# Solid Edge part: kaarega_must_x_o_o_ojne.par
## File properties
Author: Romil
Template: iso part.par
Last saved by: Romil
Revision: 40
Application: Solid Edge
Accuracy: 0.990
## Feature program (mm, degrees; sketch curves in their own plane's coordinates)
sketch for "unnamed Protrusion 1" plane through (0, 0, 0) normal (1, 0, 0) x-axis (0, 1, 0)
  line (-0.25, -3.6) -> (-7.75, -3.6)
  line (-7.75, -3.6) -> (-8, -3.6)
  arc centre (-8, 0) radius 3.6 from (-8, 3.6) to (-8, -3.6) ccw
  line (-7.75, 3.6) -> (-8, 3.6)
  line (-0.25, 3.6) -> (-7.75, 3.6)
  line (-0.25, 3.6) -> (0, 3.6)
  line (0, 3.6) -> (38.5088, 3.6)
  line (52.4, 17.4912) -> (38.5088, 3.6)
  line (52.4, 17.4912) -> (52.4, 32)
  line (59.6, 16) -> (59.6, 32)
  line (58.5456, 13.4544) -> (42.5456, -2.5456)
  line (0, -3.6) -> (40, -3.6)
  line (-0.25, -3.6) -> (0, -3.6)
extrude "unnamed Protrusion 1" add finite 7.8 along -normal
sketch for "ExtrudedCutout_39" #1 plane through (0, 0, 0) normal (1, 0, 0) x-axis (0, 1, 0)
  line (0, 0) -> (0, 0)
  line (0, 0) -> (0, 0)
  circle centre (56, 24) radius 2.4
sketch for "ExtrudedCutout_39" #2 plane through (0, 0, 0) normal (1, 0, 0) x-axis (0, 1, 0)
  arc centre (56.975, 31.025) radius 0.1 from (56.875, 31.025) to (56.975, 31.125) cw
  line (56.975, 31.125) -> (58.0449, 31.125)
  line (58.0449, 31.125) -> (58.181, 31.125)
  arc centre (56, 32) radius 2.35 from (58.181, 31.125) to (58.181, 32.875) ccw
  line (58.181, 32.875) -> (58.0449, 32.875)
  line (58.0449, 32.875) -> (56.975, 32.875)
  arc centre (56.975, 32.975) radius 0.1 from (56.975, 32.875) to (56.875, 32.975) cw
  line (56.875, 32.975) -> (56.875, 34.0449)
  line (56.875, 34.0449) -> (56.875, 34.181)
  arc centre (56, 32) radius 2.35 from (56.875, 34.181) to (55.125, 34.181) ccw
  line (55.125, 34.181) -> (55.125, 34.0449)
  line (55.125, 34.0449) -> (55.125, 32.975)
  arc centre (55.025, 32.975) radius 0.1 from (55.125, 32.975) to (55.025, 32.875) cw
  line (55.025, 32.875) -> (53.9551, 32.875)
  line (53.9551, 32.875) -> (53.819, 32.875)
  arc centre (56, 32) radius 2.35 from (53.819, 32.875) to (53.819, 31.125) ccw
  line (53.819, 31.125) -> (53.9551, 31.125)
  line (53.9551, 31.125) -> (55.025, 31.125)
  arc centre (55.025, 31.025) radius 0.1 from (55.025, 31.125) to (55.125, 31.025) cw
  line (55.125, 31.025) -> (55.125, 29.9551)
  line (55.125, 29.9551) -> (55.125, 28.9163)
  arc centre (54.825, 28.9163) radius 0.3 from (54.7182, 28.6359) to (55.125, 28.9163) ccw
  arc centre (56, 32) radius 3.6 from (54.7182, 28.6359) to (53.7108, 29.2216) cw
  arc centre (53.52, 28.9901) radius 0.3 from (53.7108, 29.2216) to (53.22, 28.9901) ccw
  line (53.22, 28.9901) -> (53.22, 26.9696)
  arc centre (53.52, 26.9696) radius 0.3 from (53.22, 26.9696) to (53.7108, 26.7381) ccw
  arc centre (56, 23.9597) radius 3.6 from (53.7108, 26.7381) to (58.2892, 26.7381) cw
  arc centre (58.48, 26.9696) radius 0.3 from (58.2892, 26.7381) to (58.78, 26.9696) ccw
  line (58.78, 28.9901) -> (58.78, 26.9696)
  arc centre (58.48, 28.9901) radius 0.3 from (58.78, 28.9901) to (58.2892, 29.2216) ccw
  arc centre (56, 32) radius 3.6 from (58.2892, 29.2216) to (57.2818, 28.6359) cw
  arc centre (57.175, 28.9163) radius 0.3 from (56.875, 28.9163) to (57.2818, 28.6359) ccw
  line (56.875, 28.9163) -> (56.875, 29.9551)
  line (56.875, 29.9551) -> (56.875, 31.025)
sketch for "ExtrudedCutout_39" #3 plane through (0, 0, 0) normal (1, 0, 0) x-axis (0, 1, 0)
  circle centre (56, 16) radius 2.4
sketch for "ExtrudedCutout_39" #4 plane through (0, 0, 0) normal (1, 0, 0) x-axis (0, 1, 0)
  line (47.3539, 3.9598) -> (52.0402, 8.6461)
  line (48.6461, 12.0402) -> (43.9598, 7.3539)
sketch for "ExtrudedCutout_39" #5 plane through (0, 0, 0) normal (1, 0, 0) x-axis (0, 1, 0)
  circle centre (40, 0) radius 2.4
sketch for "ExtrudedCutout_39" #6 plane through (0, 0, 0) normal (1, 0, 0) x-axis (0, 1, 0)
  circle centre (32, 0) radius 2.4
sketch for "ExtrudedCutout_39" #7 plane through (0, 0, 0) normal (1, 0, 0) x-axis (0, 1, 0)
  circle centre (24, 0) radius 2.4
sketch for "ExtrudedCutout_39" #8 plane through (0, 0, 0) normal (1, 0, 0) x-axis (0, 1, 0)
  circle centre (16, 0) radius 2.4
sketch for "ExtrudedCutout_39" #9 plane through (0, 0, 0) normal (1, 0, 0) x-axis (0, 1, 0)
  circle centre (8, 0) radius 2.4
sketch for "ExtrudedCutout_39" #10 plane through (0, 0, 0) normal (1, 0, 0) x-axis (0, 1, 0)
  circle centre (0, 0) radius 2.4
sketch for "ExtrudedCutout_39" #11 plane through (0, 0, 0) normal (1, 0, 0) x-axis (0, 1, 0)
  line (-5.9551, 0.875) -> (-7.025, 0.875)
  arc centre (-7.025, 0.975) radius 0.1 from (-7.025, 0.875) to (-7.125, 0.975) cw
  line (-7.125, 0.975) -> (-7.125, 2.0449)
  line (-7.125, 2.0449) -> (-7.125, 2.181)
  arc centre (-8, 0) radius 2.35 from (-7.125, 2.181) to (-8.875, 2.181) ccw
  line (-8.875, 2.181) -> (-8.875, 2.0449)
  line (-8.875, 2.0449) -> (-8.875, 0.975)
  arc centre (-8.975, 0.975) radius 0.1 from (-8.875, 0.975) to (-8.975, 0.875) cw
  line (-8.975, 0.875) -> (-10.0449, 0.875)
  line (-10.0449, 0.875) -> (-10.181, 0.875)
  arc centre (-8, 0) radius 2.35 from (-10.181, 0.875) to (-10.181, -0.875) ccw
  line (-10.181, -0.875) -> (-10.0449, -0.875)
  line (-10.0449, -0.875) -> (-8.975, -0.875)
  arc centre (-8.975, -0.975) radius 0.1 from (-8.975, -0.875) to (-8.875, -0.975) cw
  line (-8.875, -0.975) -> (-8.875, -2.0449)
  line (-8.875, -2.0449) -> (-8.875, -2.181)
  arc centre (-8, 0) radius 2.35 from (-8.875, -2.181) to (-7.125, -2.181) ccw
  line (-7.125, -2.181) -> (-7.125, -2.0449)
  line (-7.125, -2.0449) -> (-7.125, -0.975)
  arc centre (-7.025, -0.975) radius 0.1 from (-7.125, -0.975) to (-7.025, -0.875) cw
  line (-7.025, -0.875) -> (-5.9551, -0.875)
  line (-5.9551, -0.875) -> (-4.9163, -0.875)
  arc centre (-4.9163, -1.175) radius 0.3 from (-4.6359, -1.2818) to (-4.9163, -0.875) ccw
  arc centre (-8, 0) radius 3.6 from (-4.6359, -1.2818) to (-5.2216, -2.2892) cw
  arc centre (-4.9901, -2.48) radius 0.3 from (-5.2216, -2.2892) to (-4.9901, -2.78) ccw
  line (-4.9901, -2.78) -> (-2.9696, -2.78)
  arc centre (-2.9696, -2.48) radius 0.3 from (-2.9696, -2.78) to (-2.7381, -2.2892) ccw
  arc centre (0.0403, 0) radius 3.6 from (-2.7381, -2.2892) to (-2.7381, 2.2892) cw
  arc centre (-2.9696, 2.48) radius 0.3 from (-2.7381, 2.2892) to (-2.9696, 2.78) ccw
  line (-4.9901, 2.78) -> (-2.9696, 2.78)
  arc centre (-4.9901, 2.48) radius 0.3 from (-4.9901, 2.78) to (-5.2216, 2.2892) ccw
  arc centre (-8, 0) radius 3.6 from (-5.2216, 2.2892) to (-4.6359, 1.2818) cw
  arc centre (-4.9163, 1.175) radius 0.3 from (-4.9163, 0.875) to (-4.6359, 1.2818) ccw
  line (-4.9163, 0.875) -> (-5.9551, 0.875)
extrude "ExtrudedCutout_39" cut finite 28.9643 along -normal
sketch for "ExtrudedCutout_40" #1 plane through (0, 0, 0) normal (1, 0, 0) x-axis (0, 1, 0)
  arc centre (8, 0) radius 3.6 from (5.2216, 2.2892) to (5.2216, -2.2892) ccw
  arc centre (4.9901, -2.48) radius 0.3 from (5.2216, -2.2892) to (4.9901, -2.78) cw
  arc centre (4.0207, -135.1567) radius 132.3803 from (3.0524, -2.78) to (4.9901, -2.78) cw
  arc centre (3.0502, -2.48) radius 0.3 from (2.8187, -2.2892) to (3.0524, -2.78) ccw
  arc centre (3.0502, 2.48) radius 0.3 from (3.0524, 2.78) to (2.8187, 2.2892) ccw
  arc centre (4.0207, 135.1567) radius 132.3803 from (3.0524, 2.78) to (4.9901, 2.78) ccw
  arc centre (4.9901, 2.48) radius 0.3 from (4.9901, 2.78) to (5.2216, 2.2892) cw
sketch for "ExtrudedCutout_40" #2 plane through (0, 0, 0) normal (1, 0, 0) x-axis (0, 1, 0)
  arc centre (12.0207, -135.1567) radius 132.3803 from (11.0524, -2.78) to (12.9901, -2.78) cw
  arc centre (12.9901, -2.48) radius 0.3 from (13.2216, -2.2892) to (12.9901, -2.78) cw
  arc centre (16, 0) radius 3.6 from (13.2216, 2.2892) to (13.2216, -2.2892) ccw
  arc centre (12.9901, 2.48) radius 0.3 from (12.9901, 2.78) to (13.2216, 2.2892) cw
  arc centre (12.0207, 135.1567) radius 132.3803 from (11.0524, 2.78) to (12.9901, 2.78) ccw
  arc centre (11.0502, 2.48) radius 0.3 from (11.0524, 2.78) to (10.8187, 2.2892) ccw
  arc centre (8.0403, 0) radius 3.6 from (10.8187, 2.2892) to (10.8187, -2.2892) cw
  arc centre (11.0502, -2.48) radius 0.3 from (10.8187, -2.2892) to (11.0524, -2.78) ccw
sketch for "ExtrudedCutout_40" #3 plane through (0, 0, 0) normal (1, 0, 0) x-axis (0, 1, 0)
  arc centre (16.0403, 0) radius 3.6 from (18.8187, 2.2892) to (18.8187, -2.2892) cw
  arc centre (19.0502, -2.48) radius 0.3 from (18.8187, -2.2892) to (19.0524, -2.78) ccw
  arc centre (20.0207, -135.1567) radius 132.3803 from (19.0524, -2.78) to (20.9901, -2.78) cw
  arc centre (20.9901, -2.48) radius 0.3 from (21.2216, -2.2892) to (20.9901, -2.78) cw
  arc centre (24, 0) radius 3.6 from (21.2216, 2.2892) to (21.2216, -2.2892) ccw
  arc centre (20.9901, 2.48) radius 0.3 from (20.9901, 2.78) to (21.2216, 2.2892) cw
  arc centre (20.0207, 135.1567) radius 132.3803 from (19.0524, 2.78) to (20.9901, 2.78) ccw
  arc centre (19.0502, 2.48) radius 0.3 from (19.0524, 2.78) to (18.8187, 2.2892) ccw
sketch for "ExtrudedCutout_40" #4 plane through (0, 0, 0) normal (1, 0, 0) x-axis (0, 1, 0)
  arc centre (32, 0) radius 3.6 from (29.2216, 2.2892) to (29.2216, -2.2892) ccw
  arc centre (28.9901, -2.48) radius 0.3 from (29.2216, -2.2892) to (28.9901, -2.78) cw
  arc centre (28.0207, -135.1567) radius 132.3803 from (27.0524, -2.78) to (28.9901, -2.78) cw
  arc centre (27.0502, -2.48) radius 0.3 from (26.8187, -2.2892) to (27.0524, -2.78) ccw
  arc centre (24.0403, 0) radius 3.6 from (26.8187, 2.2892) to (26.8187, -2.2892) cw
  arc centre (27.0502, 2.48) radius 0.3 from (27.0524, 2.78) to (26.8187, 2.2892) ccw
  arc centre (28.0207, 135.1567) radius 132.3803 from (27.0524, 2.78) to (28.9901, 2.78) ccw
  arc centre (28.9901, 2.48) radius 0.3 from (28.9901, 2.78) to (29.2216, 2.2892) cw
sketch for "ExtrudedCutout_40" #5 plane through (0, 0, 0) normal (1, 0, 0) x-axis (0, 1, 0)
  arc centre (36.9901, -2.48) radius 0.3 from (37.2216, -2.2892) to (36.9901, -2.78) cw
  arc centre (36.0207, -135.1567) radius 132.3803 from (35.0524, -2.78) to (36.9901, -2.78) cw
  arc centre (35.0502, -2.48) radius 0.3 from (34.8187, -2.2892) to (35.0524, -2.78) ccw
  arc centre (32.0403, 0) radius 3.6 from (34.8187, 2.2892) to (34.8187, -2.2892) cw
  arc centre (35.0502, 2.48) radius 0.3 from (35.0524, 2.78) to (34.8187, 2.2892) ccw
  arc centre (36.0207, 135.1567) radius 132.3803 from (35.0524, 2.78) to (36.9901, 2.78) ccw
  arc centre (36.9901, 2.48) radius 0.3 from (36.9901, 2.78) to (37.2216, 2.2892) cw
  arc centre (40, 0) radius 3.6 from (37.2216, 2.2892) to (37.2216, -2.2892) ccw
sketch for "ExtrudedCutout_40" #6 plane through (0, 0, 0) normal (1, 0, 0) x-axis (0, 1, 0)
  arc centre (40.0285, 0.0285) radius 3.6 from (40.3744, 3.6118) to (43.6118, 0.3744) cw
  arc centre (43.9104, 0.4032) radius 0.3 from (43.6118, 0.3744) to (44.1241, 0.1926) ccw
  arc centre (138.4133, -92.7272) radius 132.3803 from (44.1241, 0.1926) to (45.4943, 1.5628) cw
  arc centre (45.2821, 1.7749) radius 0.3 from (45.311, 2.0735) to (45.4943, 1.5628) cw
  arc centre (45.6569, 5.6569) radius 3.6 from (42.0735, 5.311) to (45.311, 2.0735) ccw
  arc centre (41.7749, 5.2821) radius 0.3 from (41.5628, 5.4943) to (42.0735, 5.311) cw
  arc centre (-52.7272, 98.4133) radius 132.3803 from (40.1926, 4.1241) to (41.5628, 5.4943) ccw
  arc centre (40.4032, 3.9104) radius 0.3 from (40.1926, 4.1241) to (40.3744, 3.6118) ccw
sketch for "ExtrudedCutout_40" #7 plane through (0, 0, 0) normal (1, 0, 0) x-axis (0, 1, 0)
  arc centre (55.6253, 12.118) radius 0.3 from (55.6541, 12.4167) to (55.8374, 11.9059) cw
  arc centre (148.7564, -82.384) radius 132.3803 from (54.4673, 10.5358) to (55.8374, 11.9059) cw
  arc centre (54.2536, 10.7463) radius 0.3 from (53.955, 10.7175) to (54.4673, 10.5358) ccw
  arc centre (50.3716, 10.3716) radius 3.6 from (50.7175, 13.955) to (53.955, 10.7175) cw
  arc centre (50.7463, 14.2536) radius 0.3 from (50.5358, 14.4673) to (50.7175, 13.955) ccw
  arc centre (-42.384, 108.7564) radius 132.3803 from (50.5358, 14.4673) to (51.9059, 15.8374) ccw
  arc centre (52.118, 15.6253) radius 0.3 from (51.9059, 15.8374) to (52.4167, 15.6541) cw
  arc centre (56, 16) radius 3.6 from (52.4167, 15.6541) to (55.6541, 12.4167) ccw
sketch for "ExtrudedCutout_40" #8 plane through (0, 0, 0) normal (1, 0, 0) x-axis (0, 1, 0)
  arc centre (191.1567, 19.9793) radius 132.3803 from (58.78, 20.9476) to (58.78, 19.0099) ccw
  arc centre (58.48, 19.0099) radius 0.3 from (58.78, 19.0099) to (58.2892, 18.7784) cw
  arc centre (56, 16) radius 3.6 from (58.2892, 18.7784) to (53.7108, 18.7784) ccw
  arc centre (53.52, 19.0099) radius 0.3 from (53.7108, 18.7784) to (53.22, 19.0099) cw
  arc centre (-79.1567, 19.9793) radius 132.3803 from (53.22, 20.9476) to (53.22, 19.0099) cw
  arc centre (53.52, 20.9498) radius 0.3 from (53.7108, 21.1813) to (53.22, 20.9476) ccw
  arc centre (56, 23.9597) radius 3.6 from (58.2892, 21.1813) to (53.7108, 21.1813) cw
  arc centre (58.48, 20.9498) radius 0.3 from (58.78, 20.9476) to (58.2892, 21.1813) ccw
extrude "ExtrudedCutout_40" cut finite 3.4 along -normal
sketch for "unnamed Cutout 1" #1 plane through (0, 0, 0) normal (1, 0, 0) x-axis (0, 1, 0)
  circle centre (0, 0) radius 3.1
sketch for "unnamed Cutout 1" #2 plane through (0, 0, 0) normal (1, 0, 0) x-axis (0, 1, 0)
  circle centre (8, 0) radius 3.1
sketch for "unnamed Cutout 1" #3 plane through (0, 0, 0) normal (1, 0, 0) x-axis (0, 1, 0)
  circle centre (16, 0) radius 3.1
sketch for "unnamed Cutout 1" #4 plane through (0, 0, 0) normal (1, 0, 0) x-axis (0, 1, 0)
  circle centre (24, 0) radius 3.1
sketch for "unnamed Cutout 1" #5 plane through (0, 0, 0) normal (1, 0, 0) x-axis (0, 1, 0)
  circle centre (32, 0) radius 3.1
sketch for "unnamed Cutout 1" #6 plane through (0, 0, 0) normal (1, 0, 0) x-axis (0, 1, 0)
  circle centre (40, 0) radius 3.1
sketch for "unnamed Cutout 1" #7 plane through (0, 0, 0) normal (1, 0, 0) x-axis (0, 1, 0)
  line (43.4648, 7.8489) -> (48.1511, 12.5352)
  line (52.5352, 8.1511) -> (47.8489, 3.4648)
sketch for "unnamed Cutout 1" #8 plane through (0, 0, 0) normal (1, 0, 0) x-axis (0, 1, 0)
  circle centre (56, 16) radius 3.1
sketch for "unnamed Cutout 1" #9 plane through (0, 0, 0) normal (1, 0, 0) x-axis (0, 1, 0)
  circle centre (56, 24) radius 3.1
extrude "unnamed Cutout 1" cut finite 0.9 along -normal
mirror "unnamed Mirror 1" of "unnamed Cutout 1", "ExtrudedCutout_40" about plane through (-3.9, 0, 0) normal (1, 0, 0)
extrude "unnamed Cutout 2" cut finite 3.4
extrude "unnamed Cutout 3" cut finite 0.9
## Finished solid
Body 1: solid body, 262 faces, 654 edges, 404 vertices.
  Faces by surface: cylinder 194, plane 68
  Edges by curve: circle 388, line 266
Bounding box of the edges (mm): 7.800 x 71.200 x 39.200, from (-7.8, -11.6, -3.6) to (0, 59.6, 35.6).
Cylindrical faces by radius (mm): R0.1 x8, R0.3 x76, R2.35 x6, R2.4 x10, R3.1 x20, R3.6 x42, R132.3803 x32
Planar faces by outward normal: +x 18, +y 6, +z 6, -x 18, -y 6, -z 6, oblique 8
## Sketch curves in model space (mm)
circle centre (0, 56, 24) radius 2.4
circle centre (0, 56, 16) radius 2.4
circle centre (0, 40, 0) radius 2.4
circle centre (0, 56, 24) radius 3.1
circle centre (0, 32, 0) radius 3.1
circle centre (0, 32, 0) radius 2.4
circle centre (0, 24, 0) radius 3.1
circle centre (0, 24, 0) radius 2.4
circle centre (0, 16, 0) radius 3.1
circle centre (0, 16, 0) radius 2.4
circle centre (0, 40, 0) radius 3.1
circle centre (0, 56, 16) radius 3.1
circle centre (0, 0, 0) radius 2.4
circle centre (0, 8, 0) radius 3.1
circle centre (0, 0, 0) radius 3.1
circle centre (0, 8, 0) radius 2.4
arc centre (0, -8.975, 0.975) radius 0.1 from (0, -8.875, 0.975) through (0, -8.9064, 0.9023) to (0, -8.975, 0.875)
line (0, -8.975, 0.875) -> (0, -10.0449, 0.875)
line (0, -10.0449, 0.875) -> (0, -10.181, 0.875)
arc centre (0, -8, 0) radius 2.35 from (0, -10.181, 0.875) through (0, -10.35, 0) to (0, -10.181, -0.875)
line (0, -10.181, -0.875) -> (0, -10.0449, -0.875)
line (0, -10.0449, -0.875) -> (0, -8.975, -0.875)
arc centre (0, -8.975, -0.975) radius 0.1 from (0, -8.975, -0.875) through (0, -8.9023, -0.9064) to (0, -8.875, -0.975)
line (0, -8.875, -0.975) -> (0, -8.875, -2.0449)
line (0, -8.875, -2.0449) -> (0, -8.875, -2.181)
arc centre (0, -8, 0) radius 2.35 from (0, -8.875, -2.181) through (0, -8, -2.35) to (0, -7.125, -2.181)
line (0, -7.125, -2.181) -> (0, -7.125, -2.0449)
line (0, -7.125, -2.0449) -> (0, -7.125, -0.975)
arc centre (0, -7.025, -0.975) radius 0.1 from (0, -7.125, -0.975) through (0, -7.0936, -0.9023) to (0, -7.025, -0.875)
line (0, -7.025, -0.875) -> (0, -5.9551, -0.875)
line (0, -5.9551, -0.875) -> (0, -4.9163, -0.875)
arc centre (0, -4.9163, -1.175) radius 0.3 from (0, -4.6359, -1.2818) through (0, -4.6743, -0.9976) to (0, -4.9163, -0.875)
arc centre (0, -8, 0) radius 3.6 from (0, -4.6359, -1.2818) through (0, -4.8877, -1.8094) to (0, -5.2216, -2.2892)
arc centre (0, -4.9901, -2.48) radius 0.3 from (0, -5.2216, -2.2892) through (0, -5.2614, -2.608) to (0, -4.9901, -2.78)
line (0, -4.9901, -2.78) -> (0, -2.9696, -2.78)
arc centre (0, -2.9696, -2.48) radius 0.3 from (0, -2.9696, -2.78) through (0, -2.6983, -2.608) to (0, -2.7381, -2.2892)
arc centre (0, 0.0403, 0) radius 3.6 from (0, -2.7381, -2.2892) through (0, -3.5581, 0.1079) to (0, -2.7381, 2.2892)
arc centre (0, -2.9696, 2.48) radius 0.3 from (0, -2.7381, 2.2892) through (0, -2.6983, 2.608) to (0, -2.9696, 2.78)
line (0, -4.9901, 2.78) -> (0, -2.9696, 2.78)
arc centre (0, -4.9901, 2.48) radius 0.3 from (0, -4.9901, 2.78) through (0, -5.2614, 2.608) to (0, -5.2216, 2.2892)
arc centre (0, -8, 0) radius 3.6 from (0, -5.2216, 2.2892) through (0, -4.8877, 1.8094) to (0, -4.6359, 1.2818)
arc centre (0, -4.9163, 1.175) radius 0.3 from (0, -4.9163, 0.875) through (0, -4.6644, 1.0121) to (0, -4.6359, 1.2818)
line (0, -4.9163, 0.875) -> (0, -5.9551, 0.875)
line (0, -5.9551, 0.875) -> (0, -7.025, 0.875)
arc centre (0, -7.025, 0.975) radius 0.1 from (0, -7.025, 0.875) through (0, -7.0977, 0.9064) to (0, -7.125, 0.975)
line (0, -7.125, 0.975) -> (0, -7.125, 2.0449)
line (0, -7.125, 2.0449) -> (0, -7.125, 2.181)
arc centre (0, -8, 0) radius 2.35 from (0, -7.125, 2.181) through (0, -8, 2.35) to (0, -8.875, 2.181)
line (0, -8.875, 2.181) -> (0, -8.875, 2.0449)
line (0, -8.875, 2.0449) -> (0, -8.875, 0.975)
arc centre (0, 3.0502, -2.48) radius 0.3 from (0, 2.8187, -2.2892) through (0, 2.7793, -2.609) to (0, 3.0524, -2.78)
arc centre (0, 4.0207, -135.1567) radius 132.3803 from (0, 3.0524, -2.78) through (0, 4.0212, -2.7765) to (0, 4.9901, -2.78)
arc centre (0, 4.9901, -2.48) radius 0.3 from (0, 5.2216, -2.2892) through (0, 5.2614, -2.608) to (0, 4.9901, -2.78)
arc centre (0, 8, 0) radius 3.6 from (0, 5.2216, 2.2892) through (0, 4.4016, -0.1079) to (0, 5.2216, -2.2892)
arc centre (0, 4.9901, 2.48) radius 0.3 from (0, 4.9901, 2.78) through (0, 5.2614, 2.608) to (0, 5.2216, 2.2892)
arc centre (0, 4.0207, 135.1567) radius 132.3803 from (0, 3.0524, 2.78) through (0, 4.0212, 2.7765) to (0, 4.9901, 2.78)
arc centre (0, 3.0502, 2.48) radius 0.3 from (0, 3.0524, 2.78) through (0, 2.7793, 2.609) to (0, 2.8187, 2.2892)
arc centre (0, 0.0403, 0) radius 3.6 from (0, 2.8187, 2.2892) through (0, 3.6387, -0.1079) to (0, 2.8187, -2.2892)
line (0, -7.75, -3.6) -> (0, -8, -3.6)
line (0, -0.25, -3.6) -> (0, -7.75, -3.6)
line (0, -0.25, -3.6) -> (0, 0, -3.6)
line (0, 0, -3.6) -> (0, 40, -3.6)
arc centre (0, 40, 0) radius 3.6 from (0, 42.5456, -2.5456) through (0, 41.3777, -3.326) to (0, 40, -3.6)
line (0, 58.5456, 13.4544) -> (0, 42.5456, -2.5456)
arc centre (0, 56, 16) radius 3.6 from (0, 59.6, 16) through (0, 59.326, 14.6223) to (0, 58.5456, 13.4544)
line (0, 59.6, 16) -> (0, 59.6, 32)
arc centre (0, 56, 32) radius 3.6 from (0, 52.4, 32) through (0, 56.1067, 35.5984) to (0, 59.6, 32)
line (0, 52.4, 17.4912) -> (0, 52.4, 32)
line (0, 52.4, 17.4912) -> (0, 38.5088, 3.6)
line (0, 0, 3.6) -> (0, 38.5088, 3.6)
line (0, -0.25, 3.6) -> (0, 0, 3.6)
line (0, -0.25, 3.6) -> (0, -7.75, 3.6)
line (0, -7.75, 3.6) -> (0, -8, 3.6)
arc centre (0, -8, 0) radius 3.6 from (0, -8, 3.6) through (0, -11.5984, -0.1067) to (0, -8, -3.6)
arc centre (0, 50.3431, 10.3431) radius 3.1 from (0, 48.1511, 12.5352) through (0, 52.5992, 12.4693) to (0, 52.5352, 8.1511)
line (0, 52.5352, 8.1511) -> (0, 47.8489, 3.4648)
arc centre (0, 45.6569, 5.6569) radius 3.1 from (0, 47.8489, 3.4648) through (0, 43.4008, 3.5307) to (0, 43.4648, 7.8489)
line (0, 43.4648, 7.8489) -> (0, 48.1511, 12.5352)
arc centre (0, 45.6569, 5.6569) radius 2.4 from (0, 47.3539, 3.9598) through (0, 43.9103, 4.0108) to (0, 43.9598, 7.3539)
line (0, 47.3539, 3.9598) -> (0, 52.0402, 8.6461)
arc centre (0, 50.3431, 10.3431) radius 2.4 from (0, 48.6461, 12.0402) through (0, 52.0897, 11.9892) to (0, 52.0402, 8.6461)
line (0, 48.6461, 12.0402) -> (0, 43.9598, 7.3539)
arc centre (0, 11.0502, -2.48) radius 0.3 from (0, 10.8187, -2.2892) through (0, 10.7793, -2.609) to (0, 11.0524, -2.78)
arc centre (0, 12.0207, -135.1567) radius 132.3803 from (0, 11.0524, -2.78) through (0, 12.0212, -2.7765) to (0, 12.9901, -2.78)
arc centre (0, 12.9901, -2.48) radius 0.3 from (0, 13.2216, -2.2892) through (0, 13.2614, -2.608) to (0, 12.9901, -2.78)
arc centre (0, 16, 0) radius 3.6 from (0, 13.2216, 2.2892) through (0, 12.4016, -0.1079) to (0, 13.2216, -2.2892)
arc centre (0, 12.9901, 2.48) radius 0.3 from (0, 12.9901, 2.78) through (0, 13.2614, 2.608) to (0, 13.2216, 2.2892)
arc centre (0, 12.0207, 135.1567) radius 132.3803 from (0, 11.0524, 2.78) through (0, 12.0212, 2.7765) to (0, 12.9901, 2.78)
arc centre (0, 11.0502, 2.48) radius 0.3 from (0, 11.0524, 2.78) through (0, 10.7793, 2.609) to (0, 10.8187, 2.2892)
arc centre (0, 8.0403, 0) radius 3.6 from (0, 10.8187, 2.2892) through (0, 11.6387, -0.1079) to (0, 10.8187, -2.2892)
arc centre (0, 19.0502, -2.48) radius 0.3 from (0, 18.8187, -2.2892) through (0, 18.7793, -2.609) to (0, 19.0524, -2.78)
arc centre (0, 20.0207, -135.1567) radius 132.3803 from (0, 19.0524, -2.78) through (0, 20.0212, -2.7765) to (0, 20.9901, -2.78)
arc centre (0, 20.9901, -2.48) radius 0.3 from (0, 21.2216, -2.2892) through (0, 21.2614, -2.608) to (0, 20.9901, -2.78)
arc centre (0, 24, 0) radius 3.6 from (0, 21.2216, 2.2892) through (0, 20.4016, -0.1079) to (0, 21.2216, -2.2892)
arc centre (0, 20.9901, 2.48) radius 0.3 from (0, 20.9901, 2.78) through (0, 21.2614, 2.608) to (0, 21.2216, 2.2892)
arc centre (0, 20.0207, 135.1567) radius 132.3803 from (0, 19.0524, 2.78) through (0, 20.0212, 2.7765) to (0, 20.9901, 2.78)
arc centre (0, 19.0502, 2.48) radius 0.3 from (0, 19.0524, 2.78) through (0, 18.7793, 2.609) to (0, 18.8187, 2.2892)
arc centre (0, 16.0403, 0) radius 3.6 from (0, 18.8187, 2.2892) through (0, 19.6387, -0.1079) to (0, 18.8187, -2.2892)
arc centre (0, 27.0502, -2.48) radius 0.3 from (0, 26.8187, -2.2892) through (0, 26.7793, -2.609) to (0, 27.0524, -2.78)
arc centre (0, 28.0207, -135.1567) radius 132.3803 from (0, 27.0524, -2.78) through (0, 28.0212, -2.7765) to (0, 28.9901, -2.78)
arc centre (0, 28.9901, -2.48) radius 0.3 from (0, 29.2216, -2.2892) through (0, 29.2614, -2.608) to (0, 28.9901, -2.78)
arc centre (0, 32, 0) radius 3.6 from (0, 29.2216, 2.2892) through (0, 28.4016, -0.1079) to (0, 29.2216, -2.2892)
arc centre (0, 28.9901, 2.48) radius 0.3 from (0, 28.9901, 2.78) through (0, 29.2614, 2.608) to (0, 29.2216, 2.2892)
arc centre (0, 28.0207, 135.1567) radius 132.3803 from (0, 27.0524, 2.78) through (0, 28.0212, 2.7765) to (0, 28.9901, 2.78)
arc centre (0, 27.0502, 2.48) radius 0.3 from (0, 27.0524, 2.78) through (0, 26.7793, 2.609) to (0, 26.8187, 2.2892)
arc centre (0, 24.0403, 0) radius 3.6 from (0, 26.8187, 2.2892) through (0, 27.6387, -0.1079) to (0, 26.8187, -2.2892)
arc centre (0, 35.0502, -2.48) radius 0.3 from (0, 34.8187, -2.2892) through (0, 34.7793, -2.609) to (0, 35.0524, -2.78)
arc centre (0, 36.0207, -135.1567) radius 132.3803 from (0, 35.0524, -2.78) through (0, 36.0212, -2.7765) to (0, 36.9901, -2.78)
arc centre (0, 36.9901, -2.48) radius 0.3 from (0, 37.2216, -2.2892) through (0, 37.2614, -2.608) to (0, 36.9901, -2.78)
arc centre (0, 40, 0) radius 3.6 from (0, 37.2216, 2.2892) through (0, 36.4016, -0.1079) to (0, 37.2216, -2.2892)
arc centre (0, 36.9901, 2.48) radius 0.3 from (0, 36.9901, 2.78) through (0, 37.2614, 2.608) to (0, 37.2216, 2.2892)
arc centre (0, 36.0207, 135.1567) radius 132.3803 from (0, 35.0524, 2.78) through (0, 36.0212, 2.7765) to (0, 36.9901, 2.78)
arc centre (0, 35.0502, 2.48) radius 0.3 from (0, 35.0524, 2.78) through (0, 34.7793, 2.609) to (0, 34.8187, 2.2892)
arc centre (0, 32.0403, 0) radius 3.6 from (0, 34.8187, 2.2892) through (0, 35.6387, -0.1079) to (0, 34.8187, -2.2892)
arc centre (0, 43.9104, 0.4032) radius 0.3 from (0, 43.6118, 0.3744) through (0, 43.8101, 0.1204) to (0, 44.1241, 0.1926)
arc centre (0, 138.4133, -92.7272) radius 132.3803 from (0, 44.1241, 0.1926) through (0, 44.8067, 0.8802) to (0, 45.4943, 1.5628)
arc centre (0, 45.2821, 1.7749) radius 0.3 from (0, 45.311, 2.0735) through (0, 45.5645, 1.8762) to (0, 45.4943, 1.5628)
arc centre (0, 45.6569, 5.6569) radius 3.6 from (0, 42.0735, 5.311) through (0, 43.1887, 3.0361) to (0, 45.311, 2.0735)
arc centre (0, 41.7749, 5.2821) radius 0.3 from (0, 41.5628, 5.4943) through (0, 41.8762, 5.5645) to (0, 42.0735, 5.311)
arc centre (0, -52.7272, 98.4133) radius 132.3803 from (0, 40.1926, 4.1241) through (0, 40.8802, 4.8067) to (0, 41.5628, 5.4943)
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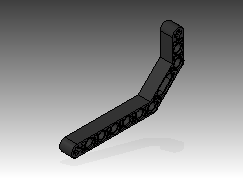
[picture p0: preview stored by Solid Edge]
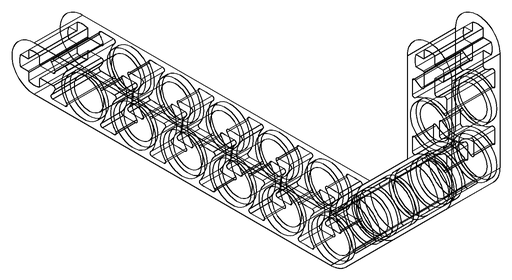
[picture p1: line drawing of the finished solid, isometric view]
